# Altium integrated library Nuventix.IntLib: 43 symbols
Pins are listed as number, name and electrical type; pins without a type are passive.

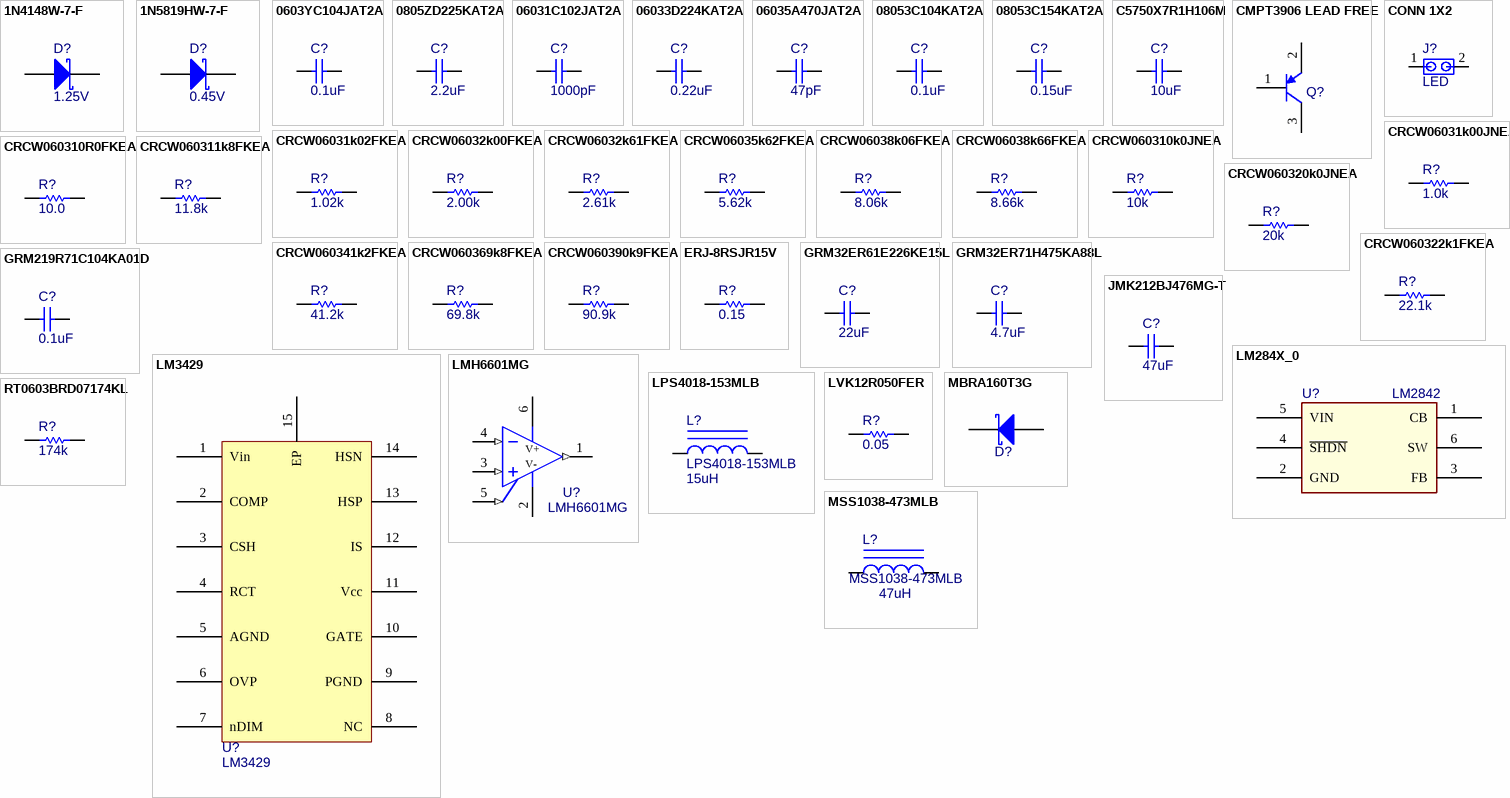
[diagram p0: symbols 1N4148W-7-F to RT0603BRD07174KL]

## 1N4148W-7-F
designator D?  value 1.25V  (hidden comment: 1N4148W-7-F)
Vr = 100V, Io = 0.15A, Vf = 1.25V; Manufacturer: Diodes Inc.; Vf_V: 1.25; Io_A: 0.15; Vr_V: 100; TJMax_C: 150; Type: Ultrafast; CompType: Diode
signal-integrity model Diode
simulation model 1N4148W
footprint SOD-123
pins: 1 A, 2 K

## 1N5819HW-7-F
designator D?  value 0.45V  (hidden comment: 1N5819HW-7-F)
Vr = 40V, Io = 1A, Vf = 0.45V; Manufacturer: Diodes Inc.; Vf_V: 0.45; Io_A: 1; Vr_V: 40; TJMax_C: 125; Type: Schottky; CompType: Diode
signal-integrity model Diode
simulation model DI_1N5819HW
footprint SOD-123
pins: 1 A, 2 K

## 0603YC104JAT2A
designator C?  value 0.1uF  (hidden comment: 0603YC104JAT2A)
Ceramic, X7R, 16V, 5%; Manufacturer: AVX; Cap_Case: 0603; ESR_Ohm: 0.039; Polarized: N; TaMax_C: 125; TaMin_C: -55; Tolerance_%: 5; VDC_V: 16; Cap_F: 100.0E-9; CompType: Capacitor; Value1: 0.039 Ohm
signal-integrity model Cap
simulation model Cap
footprint 0603
footprint 0603M
footprint 0603L
pins: 1, 2

## 0805ZD225KAT2A
designator C?  value 2.2uF  (hidden comment: 0805ZD225KAT2A)
Ceramic, X5R, 10V, 10%; Manufacturer: AVX; Cap_Case: 0805; ESR_Ohm: 0.009; Polarized: N; TaMax_C: 85; TaMin_C: -55; Tolerance_%: 10; Cap_F: 2.2E-6; CompType: Capacitor; Value1: 0.009 Ohm
signal-integrity model Cap
simulation model Cap
footprint 0805
footprint 0805M
footprint 0805L
pins: 1, 2

## 06031C102JAT2A
designator C?  value 1000pF  (hidden comment: 06031C102JAT2A)
Ceramic, X7R, 100V, 5%; Manufacturer: AVX; Cap_Case: 0603; ESR_Ohm: 0.276; Polarized: N; TaMax_C: 125; TaMin_C: -55; Tolerance_%: 5; VDC_V: 100; Cap_F: 1.0E-9; CompType: Capacitor; Value1: 0.276 Ohm
signal-integrity model Cap
simulation model Cap
footprint 0603
footprint 0603M
footprint 0603L
pins: 1, 2

## 06033D224KAT2A
designator C?  value 0.22uF  (hidden comment: 06033D224KAT2A)
Ceramic, X5R, 25V, 10%; Manufacturer: AVX; Cap_Case: 0603; ESR_Ohm: 0.036; Polarized: N; TaMax_C: 85; TaMin_C: -55; Tolerance_%: 10; VDC_V: 25; Cap_F: 220.0E-9; CompType: Capacitor; Value1: 0.036 Ohm
signal-integrity model Cap
simulation model Cap
footprint 0603
footprint 0603M
footprint 0603L
pins: 1, 2

## 06035A470JAT2A
designator C?  value 47pF  (hidden comment: 06035A470JAT2A)
Ceramic, C0G/NP0, 50V, 5%; Manufacturer: AVX; Cap_Case: 0603; ESR_Ohm: 0.174; Polarized: N; TaMax_C: 125; TaMin_C: -55; Tolerance_%: 5; VDC_V: 50; Cap_F: 47.0E-12; CompType: Capacitor; Value1: 0.174 Ohm
signal-integrity model Cap
simulation model Cap
footprint 0603
footprint 0603M
footprint 0603L
pins: 1, 2

## 08053C104KAT2A
designator C?  value 0.1uF  (hidden comment: 08053C104KAT2A)
Ceramic, X7R, 25V, 10%; Manufacturer: AVX; Cap_Case: 0805; ESR_Ohm: 0.28; Polarized: N; TaMax_C: 125; TaMin_C: -55; Tolerance_%: 10; VDC_V: 25; Cap_F: 100.0E-9; CompType: Capacitor; Value1: 0.28 Ohm
signal-integrity model Cap
simulation model Cap
footprint 0805
footprint 0805M
footprint 0805L
pins: 1, 2

## 08053C154KAT2A
designator C?  value 0.15uF  (hidden comment: 08053C154KAT2A)
Ceramic, X7R, 25V, 10%; Manufacturer: AVX; Cap_Case: 0805; ESR_Ohm: 0.02; Polarized: N; TaMax_C: 125; TaMin_C: -55; Tolerance_%: 10; VDC_V: 25; Cap_F: 150.0E-9; CompType: Capacitor; Value1: 0.02 Ohm
signal-integrity model Cap
simulation model Cap
footprint 0805
footprint 0805M
footprint 0805L
pins: 1, 2

## C5750X7R1H106M
designator C?  value 10uF  (hidden comment: C5750X7R1H106M)
Ceramic, X7R, 50V, 20%; Manufacturer: TDK; Cap_Case: 2220; ESR_Ohm: 0.003; IRMS_A: 5.5; Polarized: N; TaMax_C: 125; TaMin_C: -55; Tolerance_%: 20; VDC_V: 50; CompType: Capacitor; Cap_F: 10.0E-6; Value1: 0.003 Ohm
signal-integrity model Cap
simulation model Cap
footprint 2220
footprint 2220_M
footprint 2220_L
pins: 1, 2

## CMPT3906 LEAD FREE
designator Q?  (value not drawn)
PNP, 0.2A, 40V; Manufacturer: Central Semiconductor; CompType: BJT; PNP: 1; NPN: 0; Vceo_V: 40; Vcesat1_V: 0.25; Value: 0.25V; IcRated_A: 0.2
footprint SOT-23
pins: 1 B, 2 E, 3 C

## CONN 1X2
designator J?, comment LED
Header, TH, 100mil spacing; Manufacturer: Molex; Value: 1x2
footprint 0.1" header 2-pos (standard 0.1" headerstrip, two position)
pins: 1, 2

## CRCW06031k00JNEA
designator R?  value 1.0k  (hidden comment: CRCW06031k00JNEA)
5%, 0.1W; Manufacturer: Vishay-Dale; CompType: Resistor; Tolerance_%: 5; VDC_V: 75; Power_W: 0.1; Res_Ohm: 1000; Value_Code: 1k00; EIA_Code: E24
signal-integrity model Resistor
simulation model Resistor
footprint 0603
footprint 0603M
footprint 0603L
pins: 1, 2

## CRCW06031k02FKEA
designator R?  value 1.02k  (hidden comment: CRCW06031k02FKEA)
1%, 0.1W; Manufacturer: Vishay-Dale; CompType: Resistor; Tolerance_%: 1; VDC_V: 75; Power_W: 0.1; Res_Ohm: 1020; Value_Code: 1k02; EIA_Code: E96
signal-integrity model Resistor
simulation model Resistor
footprint 0603
footprint 0603M
footprint 0603L
pins: 1, 2

## CRCW06032k00FKEA
designator R?  value 2.00k  (hidden comment: CRCW06032k00FKEA)
1%, 0.1W; Manufacturer: Vishay-Dale; CompType: Resistor; Tolerance_%: 1; VDC_V: 75; Power_W: 0.1; Res_Ohm: 2000; Value_Code: 2k00; EIA_Code: E96
signal-integrity model Resistor
simulation model Resistor
footprint 0603
footprint 0603M
footprint 0603L
pins: 1, 2

## CRCW06032k61FKEA
designator R?  value 2.61k  (hidden comment: CRCW06032k61FKEA)
1%, 0.1W; Manufacturer: Vishay-Dale; CompType: Resistor; Tolerance_%: 1; VDC_V: 75; Power_W: 0.1; Res_Ohm: 2610; Value_Code: 2k61; EIA_Code: E96
signal-integrity model Resistor
simulation model Resistor
footprint 0603
footprint 0603M
footprint 0603L
pins: 1, 2

## CRCW06035k62FKEA
designator R?  value 5.62k  (hidden comment: CRCW06035k62FKEA)
1%, 0.1W; Manufacturer: Vishay-Dale; CompType: Resistor; Tolerance_%: 1; VDC_V: 75; Power_W: 0.1; Res_Ohm: 5620; Value_Code: 5k62; EIA_Code: E96
signal-integrity model Resistor
simulation model Resistor
footprint 0603
footprint 0603M
footprint 0603L
pins: 1, 2

## CRCW06038k06FKEA
designator R?  value 8.06k  (hidden comment: CRCW06038k06FKEA)
1%, 0.1W; Manufacturer: Vishay-Dale; CompType: Resistor; Tolerance_%: 1; VDC_V: 75; Power_W: 0.1; Res_Ohm: 8060; Value_Code: 8k06; EIA_Code: E96
signal-integrity model Resistor
simulation model Resistor
footprint 0603
footprint 0603M
footprint 0603L
pins: 1, 2

## CRCW06038k66FKEA
designator R?  value 8.66k  (hidden comment: CRCW06038k66FKEA)
1%, 0.1W; Manufacturer: Vishay-Dale; CompType: Resistor; Tolerance_%: 1; VDC_V: 75; Power_W: 0.1; Res_Ohm: 8660; Value_Code: 8k66; EIA_Code: E96
signal-integrity model Resistor
simulation model Resistor
footprint 0603
footprint 0603M
footprint 0603L
pins: 1, 2

## CRCW060310k0JNEA
designator R?  value 10k  (hidden comment: CRCW060310k0JNEA)
5%, 0.1W; Manufacturer: Vishay-Dale; CompType: Resistor; Tolerance_%: 5; VDC_V: 75; Power_W: 0.1; Res_Ohm: 10000; Value_Code: 10k0; EIA_Code: E24
signal-integrity model Resistor
simulation model Resistor
footprint 0603
footprint 0603M
footprint 0603L
pins: 1, 2

## CRCW060310R0FKEA
designator R?  value 10.0  (hidden comment: CRCW060310R0FKEA)
1%, 0.1W; Manufacturer: Vishay-Dale; CompType: Resistor; Tolerance_%: 1; VDC_V: 75; Power_W: 0.1; Res_Ohm: 10; Value_Code: 10R0; EIA_Code: E96
signal-integrity model Resistor
simulation model Resistor
footprint 0603
footprint 0603M
footprint 0603L
pins: 1, 2

## CRCW060311k8FKEA
designator R?  value 11.8k  (hidden comment: CRCW060311k8FKEA)
1%, 0.1W; Manufacturer: Vishay-Dale; CompType: Resistor; Tolerance_%: 1; VDC_V: 75; Power_W: 0.1; Res_Ohm: 11800; Value_Code: 11k8; EIA_Code: E96
signal-integrity model Resistor
simulation model Resistor
footprint 0603
footprint 0603M
footprint 0603L
pins: 1, 2

## CRCW060320k0JNEA
designator R?  value 20k  (hidden comment: CRCW060320k0JNEA)
5%, 0.1W; Manufacturer: Vishay-Dale; CompType: Resistor; Tolerance_%: 5; VDC_V: 75; Power_W: 0.1; Res_Ohm: 20000; Value_Code: 20k0; EIA_Code: E24
signal-integrity model Resistor
simulation model Resistor
footprint 0603
footprint 0603M
footprint 0603L
pins: 1, 2

## CRCW060322k1FKEA
designator R?  value 22.1k  (hidden comment: CRCW060322k1FKEA)
1%, 0.1W; Manufacturer: Vishay-Dale; CompType: Resistor; Tolerance_%: 1; VDC_V: 75; Power_W: 0.1; Res_Ohm: 22100; Value_Code: 22k1; EIA_Code: E96
signal-integrity model Resistor
simulation model Resistor
footprint 0603
footprint 0603M
footprint 0603L
pins: 1, 2

## CRCW060341k2FKEA
designator R?  value 41.2k  (hidden comment: CRCW060341k2FKEA)
1%, 0.1W; Manufacturer: Vishay-Dale; CompType: Resistor; Tolerance_%: 1; VDC_V: 75; Power_W: 0.1; Res_Ohm: 41200; Value_Code: 41k2; EIA_Code: E96
signal-integrity model Resistor
simulation model Resistor
footprint 0603
footprint 0603M
footprint 0603L
pins: 1, 2

## CRCW060369k8FKEA
designator R?  value 69.8k  (hidden comment: CRCW060369k8FKEA)
1%, 0.1W; Manufacturer: Vishay-Dale; CompType: Resistor; Tolerance_%: 1; VDC_V: 75; Power_W: 0.1; Res_Ohm: 69800; Value_Code: 69k8; EIA_Code: E96
signal-integrity model Resistor
simulation model Resistor
footprint 0603
footprint 0603M
footprint 0603L
pins: 1, 2

## CRCW060390k9FKEA
designator R?  value 90.9k  (hidden comment: CRCW060390k9FKEA)
1%, 0.1W; Manufacturer: Vishay-Dale; CompType: Resistor; Tolerance_%: 1; VDC_V: 75; Power_W: 0.1; Res_Ohm: 90900; Value_Code: 90k9; EIA_Code: E96
signal-integrity model Resistor
simulation model Resistor
footprint 0603
footprint 0603M
footprint 0603L
pins: 1, 2

## ERJ-8RSJR15V
designator R?  value 0.15  (hidden comment: ERJ-8RSJR15V)
5%, 0.25W; Manufacturer: Panasonic; CompType: Resistor; Tolerance_%: 5; Power_W: 0.25; Value_Code: R150; EIA_Code: E24
signal-integrity model Resistor
simulation model Resistor
footprint 1206
footprint 1206M
footprint 1206L
pins: 1, 2

## GRM32ER61E226KE15L
designator C?  value 22uF  (hidden comment: GRM32ER61E226KE15L)
Ceramic, X5R, 25V, 10%; Manufacturer: MuRata; Cap_Case: 1210; ESR_Ohm: 0.002; Polarized: N; TaMax_C: 85; TaMin_C: -55; Tolerance_%: 10; VDC_V: 25; Cap_F: 22.0E-6; CompType: Capacitor; Value1: 0.002 Ohm
signal-integrity model Cap
simulation model Cap
footprint 1210
footprint 1210M
footprint 1210L
pins: 1, 2

## GRM32ER71H475KA88L
designator C?  value 4.7uF  (hidden comment: GRM32ER71H475KA88L)
Ceramic, X7R, 50V, 10%; Manufacturer: MuRata; Cap_Case: 1210; ESR_Ohm: 0.002; Polarized: N; TaMax_C: 125; TaMin_C: -55; Tolerance_%: 10; VDC_V: 50; Cap_F: 4.7E-6; CompType: Capacitor; Value1: 0.002 Ohm
signal-integrity model Cap
simulation model Cap
footprint 1210
footprint 1210M
footprint 1210L
pins: 1, 2

## GRM219R71C104KA01D
designator C?  value 0.1uF  (hidden comment: GRM219R71C104KA01D)
Ceramic, X7R, 16V, 10%; Manufacturer: MuRata; Cap_Case: 0805; Polarized: N; TaMax_C: 125; TaMin_C: -55; Tolerance_%: 10; VDC_V: 16; Cap_F: 100.0E-9; CompType: Capacitor
signal-integrity model Cap
simulation model Cap
footprint 0805
footprint 0805M
footprint 0805L
pins: 1, 2

## JMK212BJ476MG-T
designator C?  value 47uF  (hidden comment: JMK212BJ476MG-T)
Ceramic, X5R, 6.3V, 20%; Manufacturer: Taiyo Yuden; Cap_Case: 0805; Polarized: N; TaMax_C: 85; TaMin_C: -55; Tolerance_%: 20; VDC_V: 6.3; Cap_F: 47.0E-6; CompType: Capacitor
signal-integrity model Cap
simulation model Cap
footprint 0805
footprint 0805M
footprint 0805L
pins: 1, 2

## LM284X_0
designator U?, comment LM2842
300 mA/600 mA up to 42V Input Step-Down DC/DC Regulator in Thin SOT-23; Manufacturer: National Semiconductor; PartNumber: LM2842XMK-ADJL
footprint SOT23-6
footprint SOT23-6
footprint MK06A
pins: 1 CB, 2 GND (power), 3 FB, 4 ~{SHDN}, 5 VIN, 6 SW

## LM3429
designator U?
N-Channel Controller for Constant Current LED Drivers; Manufacturer: National Semiconductor; PartNumber: LM3429MH
footprint TSSOP-14_EP
pins: 1 Vin, 2 COMP, 3 CSH, 4 RCT, 5 AGND, 6 OVP, 7 nDIM, 8 NC, 9 PGND, 10 GATE, 11 Vcc, 12 IS, 13 HSP, 14 HSN, 15 EP

## LMH6601MG
designator U?
2.4V R-R Out CMOS Video OpAmp with Shutdown; Manufacturer: National Semiconductor; CompType: OpAmp IC; TaMin_C: -40.0; TaMax_C: 85.0; Sim Note: Shutdown not modeled
3D model MAA06A
footprint MAA06A
footprint MAA06AL
footprint MAA06AM
simulation model LMH6601 (SUBCKT)
pins: 1 OUT (out), 2 V- (power), 3 IN+ (in), 4 IN- (in), 5 SD (in), 6 V+ (power)
1 alternate drawing of the same symbol

## LPS4018-153MLB
designator L?  value 15uH
Shielded Drum Core, 0.94A, 0.26 Ohm; Manufacturer: Coilcraft Inc.; CompType: Inductor; Ind_H: 15.0E-6; DCR_Ohm: 0.26; Imax_A: 0.94; Material: Ferrite
signal-integrity model Inductor
simulation model Inductor
footprint LPS4018
pins: 1, 2

## LVK12R050FER
designator R?  value 0.05  (hidden comment: LVK12R050FER)
1%, 0.5W; Manufacturer: Ohmite; CompType: Resistor; Tolerance_%: 1; Power_W: 0.5; Value_Code: R050; EIA_Code: E96
signal-integrity model Resistor
simulation model Resistor
footprint 1206
footprint 1206M
footprint 1206L
pins: 1, 2

## MBRA160T3G
designator D?  (value not drawn)
Vr = 60V, Io = 1A, Vf = 0.51V; Manufacturer: ON Semiconductor; RJC_CperW: 35; Vf_V: 0.51; Io_A: 1; Vr_V: 60; TJMax_C: 150; Type: Schottky; CompType: Diode
simulation model mbra160t3
footprint SMA
pins: 1 A, 2 K

## MSS1038-473MLB
designator L?  value 47uH  (hidden comment: MSS1038-473MLB)
Shielded Drum Core, 2.25A, 0.112 Ohm; Manufacturer: Coilcraft Inc.; CompType: Inductor; Ind_H: 47.0E-6; DCR_Ohm: 0.112; Imax_A: 2.25; Material: Ferrite
signal-integrity model Inductor
simulation model Inductor
footprint MSS1038
pins: 1, 2

## RT0603BRD07174KL
designator R?  value 174k  (hidden comment: RT0603BRD07174KL)
0.1%, 0.1W; Manufacturer: Yageo America; CompType: Resistor; Tolerance_%: 0.1; VDC_V: 75; Res_Ohm: 174000; EIA_Code: E192
signal-integrity model Resistor
simulation model Resistor
footprint 0603
footprint 0603M
footprint 0603L
pins: 1, 2

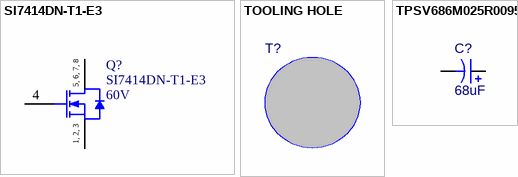
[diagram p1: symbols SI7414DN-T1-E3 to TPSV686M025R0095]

## SI7414DN-T1-E3
designator Q?  value 60V
5.6A, 16nC, rDS(on) @ 4.5V =0.036 Ohm; Manufacturer: Vishay-Siliconix; CompType: MOSFET; ChType: N; VdsMax_V: 60; Rdson45_Ohm: 0.036; QgTyp_nC: 16; Vgs_V: 20; IdsMax_A: 5.6
footprint PowerPAK_1212-8
footprint PowerPAK_1212-8_NoVias
simulation model Si7414DN
footprint 1212-8 Powerpack_smask
pins: 1 S, 2 S, 3 S, 4 G, 5 D, 6 D, 7 D, 8 D, 9 D

## TOOLING HOLE
designator T?  (value not drawn)  (no BOM)
footprint 4-40 Mounting Hole (Tooling Hole)

## TPSV686M025R0095
designator C?  value 68uF  (hidden comment: TPSV686M025R0095)
TA, 25V, 20%, 0.095 Ohm ESR; Manufacturer: AVX; Cap_Case: V; ESR_Ohm: 0.095; IRMS_A: 1.46; Polarized: Y; TaMax_C: 125; TaMin_C: -55; Tolerance_%: 20; VDC_V: 25; Cap_F: 68.0E-6; CompType: Capacitor; Dielectric: TPS
signal-integrity model Cap
simulation model Cap
footprint 7361-38
pins: 1 +, 2 -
